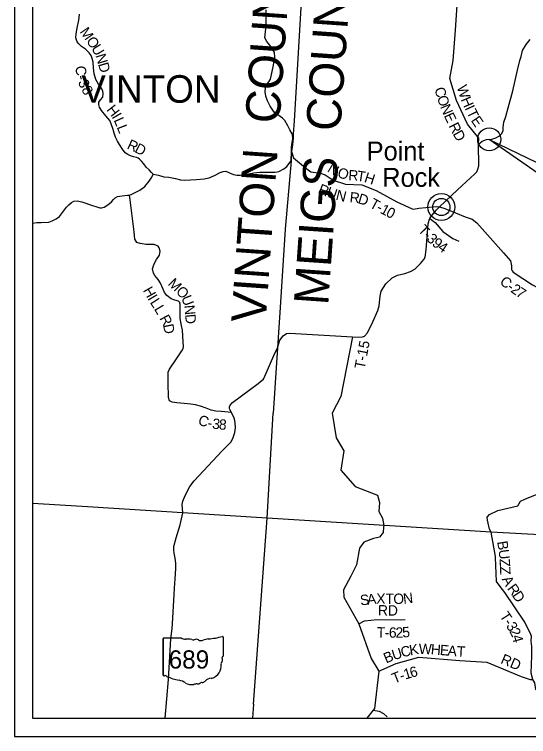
# Model space of a CAD drawing. Extents: x -84548 to 2262448, y -162180 to 525962.
# Drawn here: x -37475 to -22558, y 130056 to 150992 of the extents above; entities that cross this region are included whole.
import ezdxf

# ---------------------------------------------------------------- set-up
doc = ezdxf.new("R2010")
doc.units = 0
for name, color, linetype in [('GM_X_Adjacent_County_Text', 7, 'Continuous'), ('GM_X_City_Street', 7, 'Continuous'), ('GM_X_City_Street_Text', 7, 'Continuous'), ('GM_X_Corporation_Text', 7, 'Continuous'), ('GM_X_County', 7, 'Continuous'), ('GM_X_County_Road', 7, 'Continuous'), ('GM_X_Hydro', 7, 'Continuous'), ('GM_X_Major_Lake', 7, 'Continuous'), ('GM_X_Major_Lake_Text', 7, 'Continuous'), ('GM_X_Major_River', 7, 'Continuous'), ('GM_X_Minor_Lake', 7, 'Continuous'), ('GM_X_Minor_River_Text', 7, 'Continuous'), ('GM_X_Rail_Line', 7, 'Continuous'), ('GM_X_Section', 7, 'Continuous'), ('GM_X_Township_Road', 7, 'Continuous')]:
    doc.layers.add(name, color=color, linetype=linetype)

msp = doc.modelspace()

# ---------------------------------------------------------------- linework, layer by layer
at = {"layer": 'GM_X_Adjacent_County_Text'}
msp.add_circle((-23698, 147370), 334, dxfattribs=at)
at = {"layer": 'GM_X_City_Street'}
for p, q in [((-30138, 136391), (-29965, 139433)), ((-30539, 130996), (-30138, 136391))]:
    msp.add_line(p, q, dxfattribs=at)
at = {"layer": 'GM_X_County'}
for p, q in [((-37475, 167016), (-37475, 130056)), ((-36947, 166488), (-36947, 130584)), ((-36947, 166488), (-36947, 130584)), ((-36947, 130584), (-1043, 130584)), ((-36947, 130584), (-1043, 130584)), ((-37475, 130056), (-515, 130056))]:
    msp.add_line(p, q, dxfattribs=at)
at = {"layer": 'GM_X_Hydro'}
for p, q in [((-35513, 136724), (-36947, 136815)), ((-30138, 136391), (-35513, 136724)), ((-23639, 135977), (-30138, 136391)), ((-19190, 135747), (-23639, 135977)), ((-30539, 130996), (-30565, 130584))]:
    msp.add_line(p, q, dxfattribs=at)
at = {"layer": 'GM_X_Major_Lake'}
for p, q in [((-29155, 151361), (-29360, 147907)), ((-29360, 147907), (-29388, 147517)), ((-29390, 147404), (-29406, 147216)), ((-29388, 147517), (-29390, 147404)), ((-29406, 147216), (-29433, 147017)), ((-29433, 147017), (-29449, 146744)), ((-29449, 146744), (-29615, 144771)), ((-29615, 144771), (-29777, 142346)), ((-29777, 142346), (-29965, 139433))]:
    msp.add_line(p, q, dxfattribs=at)
at = {"layer": 'GM_X_Major_Lake_Text'}
for points in [[(-29843, 141330), (-29779, 141548), (-29675, 141670), (-29583, 141737), (-29482, 141751), (-27668, 141649), (-27506, 141639), (-27373, 141640), (-27315, 141664), (-27231, 141762), (-27076, 142081), (-26928, 142408), (-26892, 142539), (-26860, 142821), (-26834, 142972), (-26695, 143182), (-26515, 143353), (-26362, 143430), (-26152, 143482), (-25980, 143536), (-25856, 143605), (-25690, 143775), (-25594, 143884), (-25556, 143956), (-25532, 144165), (-25469, 144918), (-25441, 145031), (-25418, 145078), (-25397, 145119), (-25240, 145314), (-25139, 145410), (-24619, 145906), (-24113, 146368), (-24061, 146430), (-24029, 146508), (-24004, 146607), (-24006, 147234), (-23902, 147314), (-23774, 147362), (-23622, 147379), (-23506, 147415), (-23403, 147470), (-23339, 147529), (-23296, 147618), (-23293, 147718), (-23273, 147871), (-23219, 148036), (-23148, 148281), (-23019, 148778), (-22882, 149379), (-22811, 149652), (-22776, 149773), (-22732, 149942), (-22626, 150117), (-22507, 150261)], [(-33102, 130584), (-33004, 131710), (-32937, 132890), (-32902, 133187), (-32888, 133337), (-32836, 134164), (-32831, 134361), (-32811, 134631), (-32792, 134928), (-32788, 135084), (-32812, 135231), (-32842, 135376), (-32853, 135466), (-32847, 135570), (-32783, 135814), (-32667, 136192), (-32592, 136543), (-32605, 136788), (-32587, 136880), (-32523, 137040), (-32382, 137306), (-32256, 137471), (-31443, 138335), (-31190, 138600), (-31126, 138730), (-31078, 138871), (-31060, 139009), (-31066, 139152), (-31077, 139222), (-31098, 139291), (-31176, 139450), (-31222, 139541), (-31230, 139577), (-31232, 139611), (-31218, 139659), (-31148, 139737), (-30406, 140290), (-30284, 140384), (-30246, 140420), (-30170, 140591), (-29950, 141101), (-29843, 141330)]]:
    msp.add_lwpolyline(points, dxfattribs=at)
at = {"layer": 'GM_X_Major_River'}
for radius in [393, 249]:
    msp.add_circle((-25088, 145408), radius, dxfattribs=at)
at = {"layer": 'GM_X_Minor_Lake'}
for points in [[(-24006, 147234), (-24003, 147400), (-24326, 147809), (-24651, 148495), (-24842, 149138), (-24746, 149656), (-24677, 150538), (-24633, 151264)], [(-29433, 147017), (-29436, 147130), (-29431, 147221), (-29401, 147399), (-29404, 147494), (-29413, 147532), (-29485, 147642), (-29547, 147766), (-29634, 147916), (-29695, 147980), (-29938, 148161), (-30053, 148331), (-30133, 148485), (-30184, 148619), (-30198, 148751), (-30188, 148875), (-30161, 148953), (-30097, 149040), (-30043, 149118), (-29966, 149476), (-29921, 149751), (-29932, 149885), (-30040, 150061), (-30153, 150209), (-30205, 150315), (-30168, 150665), (-30174, 150977), (-30170, 151125)], [(-29433, 147017), (-29376, 146839), (-29261, 146738), (-29025, 146549), (-28879, 146426), (-28598, 146388), (-28462, 146340), (-28223, 146188), (-27874, 146074), (-27399, 146048), (-26982, 145890), (-26380, 145561), (-25933, 145359), (-25932, 145358)], [(-25932, 145358), (-25898, 145343), (-25742, 145377), (-25339, 145412), (-25215, 145420), (-25139, 145410)], [(-25418, 145078), (-25265, 144956), (-25048, 144702), (-24753, 144497), (-24584, 144417)], [(-27668, 141649), (-28005, 139915), (-28256, 139428), (-28138, 138720), (-27917, 138336), (-28005, 137775), (-27592, 137303), (-26943, 137052), (-26884, 136845), (-26898, 136580), (-26795, 136388), (-26757, 136176), (-26762, 136125)], [(-23687, 136067), (-23688, 136069), (-23747, 136328), (-23755, 136415), (-23692, 136491), (-23452, 136613), (-22869, 136745), (-22790, 136882), (-22666, 136939), (-22260, 137101), (-21781, 137046), (-21437, 137078), (-21126, 137044), (-20859, 137025), (-20194, 137164), (-19924, 137208)], [(-26762, 136125), (-26776, 135972), (-26886, 135833), (-27061, 135798), (-27341, 135694), (-27459, 135517), (-27548, 135030), (-27710, 134706), (-27931, 134307), (-27917, 134100), (-27480, 133323), (-27120, 132315), (-26901, 131953), (-27031, 130869), (-27071, 130817), (-27247, 130584)], [(-23516, 135249), (-23517, 135272), (-23639, 135977), (-23687, 136067)], [(-21591, 130584), (-21705, 130712), (-22344, 131416), (-22376, 131611), (-22433, 131714), (-22481, 131889), (-22467, 132399), (-22464, 132666), (-22479, 132817), (-22473, 132969), (-22495, 133014), (-22669, 133371), (-23242, 134235), (-23385, 134405), (-23487, 134553), (-23516, 135246), (-23516, 135249)], [(-27480, 133323), (-27319, 133406), (-26950, 133452), (-26271, 133436), (-26141, 133451)], [(-26901, 131953), (-26395, 132177), (-25743, 132354), (-24553, 132256), (-23768, 132217), (-22768, 131796), (-22510, 131713), (-22433, 131714)], [(-27071, 130817), (-26889, 130787), (-26763, 130721), (-26656, 130623)]]:
    msp.add_lwpolyline(points, dxfattribs=at)
at = {"layer": 'GM_X_Minor_River_Text'}
msp.add_line((-29449, 146744), (-29433, 147017), dxfattribs=at)
for points in [[(-33452, 146363), (-33500, 146405), (-33570, 146489), (-33651, 146566), (-33721, 146656), (-33789, 146738), (-33848, 146800), (-33882, 146828), (-33936, 146846), (-34024, 146868), (-34104, 146896), (-34184, 146927), (-34265, 146979), (-34343, 147089), (-34427, 147223), (-34486, 147317), (-34542, 147431), (-34581, 147553), (-34611, 147657), (-34668, 147817), (-34710, 147917), (-34824, 148049), (-34949, 148203), (-35011, 148307), (-35030, 148377), (-35028, 148453), (-34982, 148515), (-34914, 148597), (-34901, 148693), (-34911, 148777), (-34959, 148863), (-35034, 148973), (-35108, 149107), (-35161, 149269), (-35181, 149447), (-35192, 149608), (-35218, 149716), (-35247, 149798), (-35303, 149881), (-35415, 149983), (-35526, 150065), (-35606, 150135), (-35650, 150195), (-35691, 150309), (-35687, 150427), (-35656, 150589), (-35604, 150828), (-35583, 151002)], [(-36947, 144940), (-36827, 144955), (-36697, 144961), (-36477, 144972), (-36379, 145004), (-36263, 145066), (-36166, 145137), (-36048, 145285), (-35960, 145404), (-35900, 145476), (-35821, 145540), (-35753, 145580), (-35659, 145590), (-35523, 145563), (-35212, 145457), (-35088, 145412), (-35000, 145384), (-34944, 145380), (-34868, 145400), (-34760, 145469), (-34654, 145557), (-34598, 145625), (-34548, 145671), (-34480, 145716), (-34350, 145734), (-34194, 145750), (-34132, 145754), (-34068, 145777), (-33951, 145837), (-33835, 145901), (-33689, 146008), (-33563, 146158), (-33486, 146269), (-33452, 146363), (-33298, 146333), (-33142, 146287), (-32995, 146270), (-32797, 146232), (-32659, 146194), (-32539, 146187), (-32195, 146206), (-31971, 146228), (-31829, 146257), (-31671, 146323), (-31505, 146410), (-31419, 146440), (-31341, 146444), (-31237, 146402), (-31117, 146354), (-31020, 146327), (-30928, 146329), (-30734, 146361), (-30532, 146400), (-30352, 146418), (-30016, 146415), (-29906, 146420), (-29808, 146440), (-29656, 146516), (-29572, 146585), (-29449, 146744)], [(-31176, 139450), (-31373, 139469), (-31480, 139479), (-31630, 139494), (-31762, 139516), (-31914, 139572), (-32078, 139631), (-32219, 139677), (-32355, 139693), (-32551, 139710), (-32759, 139730), (-32901, 139748), (-32941, 139765), (-32978, 139793), (-33008, 139883), (-33011, 140310), (-33016, 140502), (-33012, 140618), (-32973, 140712), (-32774, 141009), (-32614, 141236), (-32576, 141304), (-32567, 141354), (-32577, 141498), (-32602, 141836), (-32631, 141972), (-32663, 142173), (-32666, 142335), (-32667, 142535), (-32669, 142595), (-32671, 142621), (-32677, 142643), (-32711, 142681), (-32823, 142711), (-32925, 142746), (-33056, 142840), (-33120, 142926), (-33169, 143050), (-33235, 143196), (-33308, 143308), (-33402, 143420), (-33442, 143486), (-33473, 143620), (-33421, 143760), (-33348, 143889), (-33270, 144017), (-33250, 144127), (-33271, 144221), (-33309, 144273), (-33419, 144317), (-33655, 144326), (-33823, 144348), (-33920, 144380), (-33978, 144474), (-33999, 144686), (-34114, 145620), (-34132, 145754)], [(-25139, 145410), (-24987, 145364), (-24674, 145235), (-24402, 145124), (-24195, 145054), (-24059, 144947), (-23288, 144083), (-23078, 143852), (-23056, 143706), (-23053, 143601), (-23035, 143557), (-23002, 143523), (-22447, 143149), (-22209, 143029), (-21871, 142513), (-21621, 141908), (-21398, 141679), (-21156, 141593), (-21000, 141614)]]:
    msp.add_lwpolyline(points, dxfattribs=at)
at = {"layer": 'GM_X_Rail_Line'}
for p, q in [((-33160, 132895), (-33160, 131838)), ((-33160, 131838), (-33160, 132895)), ((-33160, 131838), (-33160, 132895)), ((-33143, 132913), (-32633, 132913)), ((-31420, 132939), (-31420, 132387)), ((-31420, 132387), (-31420, 132387))]:
    msp.add_line(p, q, dxfattribs=at)
for centre, major_axis, start_param, end_param in [((-32040, 134354), (1845, 0), 4.814394, 5.042369), ((-31439, 132942), (19.4, 0), 6.141152, 7.989035), ((-33140, 132897), (20.2, 0), 1.712693, 3.28349), ((-32512, 133036), (196, 0), 4.042523, 4.731795), ((-32447, 132320), (702, 0), 1.404758, 1.657858), ((-32288, 132903), (56.4, 0), 3.836095, 5.185415), ((-32205, 132781), (117, 0), 0.950623, 2.079405), ((-32054, 132948), (141, 0), 4.081561, 5.145723), ((-31805, 132591), (371, 0), 1.699011, 2.107814), ((-31424, 132346), (30, 0), 1.883978, 3.671073), ((-31615, 132276), (180, 0), 5.934695, 6.695948), ((-31441, 132385), (20.7, 0), 5.05454, 6.418171), ((-31937, 132085), (462, 0), 5.101752, 6.440018), ((-31351, 132155), (131, 0), 2.387724, 3.262537), ((-33140, 131836), (20.3, 0), 3.00124, 4.508301), ((-33137, 131944), (155, 0), 4.665946, 4.897461), ((-33105, 131777), (56, 0), 0.519207, 1.627899), ((-32399, 132727), (1333, 0), 4.195997, 4.488961), ((-31742, 131542), (253, 0), 1.647645, 2.488434), ((-32796, 131364), (417, 0), 0.823519, 1.323587), ((-32345, 131772), (265, 0), 4.026481, 4.996735), ((-32192, 131407), (217, 0), 1.495662, 1.94098), ((-32173, 131693), (141, 0), 4.691044, 5.507374), ((-32045, 131591), (39.7, 0), 1.147584, 2.315152), ((-32062, 131736), (149, 0), 4.937069, 5.64225)]:
    msp.add_ellipse(centre, major_axis=major_axis, ratio=0.8, start_param=start_param, end_param=end_param, dxfattribs=at)
at = {"layer": 'GM_X_Section'}
msp.add_lwpolyline([(-20640, 145240), (-23698, 147370), (-19294, 145240)], close=True, dxfattribs=at)

# ---------------------------------------------------------------- texts
at = {"layer": 'GM_X_Adjacent_County_Text'}
for s, p in [('Point', (-27254, 146757)), ('Rock', (-26803, 145994))]:
    msp.add_text(s, height=550, rotation=0, dxfattribs=at).set_placement(p)
at = {"layer": 'GM_X_City_Street_Text'}
for s, p in [('VINTON  COUNTY', (-30187, 142028)), ('MEIGS  COUNTY', (-28372, 142544))]:
    msp.add_text(s, height=1000, rotation=86.0177, dxfattribs=at).set_placement(p)
at = {"layer": 'GM_X_Corporation_Text'}
msp.add_text('VINTON', height=800, rotation=0, dxfattribs=at).set_placement((-35536, 148431))
at = {"layer": 'GM_X_County_Road'}
for s, rotation, p in [('M', 305.1287, (-35592, 150488)), ('O', 305.0905, (-35405, 150222)), ('U', 301.3374, (-35256, 150010)), ('N', 286.739, (-35127, 149803)), ('C', 274.8453, (-35704, 149491)), ('D', 286.3057, (-35051, 149551)), ('3', 290.86, (-35635, 149037)), ('-', 283.1188, (-35676, 149199)), ('8', 301.5722, (-35542, 148809)), ('H', 307.8986, (-34816, 148226)), ('I', 300.289, (-34660, 148027)), ('L', 294.0574, (-34601, 147928)), ('L', 291.343, (-34511, 147726)), ('R', 335.4914, (-34230, 147111)), ('D', 332.7768, (-34009, 147011)), ('M', 315.3133, (-33040, 143168)), ('C', 320.021, (-23418, 143206)), ('H', 299.3861, (-33755, 142995)), ('O', 315, (-32809, 142939)), ('-', 326.1692, (-23201, 143026)), ('2', 325.9982, (-23099, 142958)), ('7', 326.3742, (-22944, 142853)), ('I', 300.2356, (-33623, 142760)), ('U', 291.1777, (-32640, 142780)), ('L', 302.9032, (-33553, 142641)), ('L', 300.4221, (-33433, 142455)), ('N', 275.5091, (-32549, 142555)), ('R', 298.1345, (-33274, 142185)), ('D', 275.326, (-32524, 142292)), ('D', 281.3221, (-33165, 141989)), ('C', 340.2023, (-32172, 139113)), ('3', 352.5968, (-31750, 138988)), ('8', 355.0635, (-31553, 138963)), ('-', 348.6688, (-31893, 139016))]:
    msp.add_text(s, height=300, rotation=rotation, dxfattribs=at).set_placement(p)
at = {"layer": 'GM_X_Rail_Line'}
msp.add_text('689', height=528, dxfattribs=at).set_placement((-33001, 132027))
at = {"layer": 'GM_X_Township_Road'}
for s, rotation, p in [('C', 286.663, (-25294, 148834)), ('W', 287.4611, (-24644, 148890)), ('O', 288.5918, (-25220, 148588)), ('H', 293.1972, (-24529, 148528)), ('N', 292.5151, (-25128, 148316)), ('I', 295.1151, (-24420, 148275)), ('T', 296.0744, (-24366, 148159)), ('E', 295.0778, (-25021, 148059)), ('E', 304.4273, (-24243, 147917)), ('R', 296.5174, (-24883, 147765)), ('D', 299.1537, (-24766, 147531)), ('N', 329.3261, (-28419, 146447)), ('O', 342.0592, (-28126, 146283)), ('R', 356.3874, (-27794, 146186)), ('T', 351.1711, (-27556, 146171)), ('H', 341.921, (-27346, 146140)), ('R', 339.346, (-28684, 145808)), ('U', 341.0357, (-28444, 145718)), ('N', 345.9273, (-28168, 145624)), ('R', 354.1156, (-27759, 145547)), ('D', 342.9988, (-27529, 145524)), ('T', 331.5113, (-27194, 145414)), ('-', 331.5767, (-26997, 145307)), ('1', 331.7793, (-26887, 145248)), ('0', 332.8943, (-26719, 145158)), ('T', 313.6968, (-25787, 144721)), ('-', 314.2524, (-25630, 144556)), ('3', 316.2178, (-25536, 144460)), ('9', 321.6631, (-25379, 144312)), ('4', 326.0153, (-25214, 144182)), ('T-15', 78.9675, (-27319, 140695)), ('B', 279.0119, (-23471, 135704)), ('U', 276.9362, (-23433, 135464)), ('Z', 273.1644, (-23402, 135207)), ('Z', 272.3578, (-23389, 134984)), ('A', 298.0937, (-23342, 134619)), ('R', 306.4686, (-23192, 134345)), ('X', 359.4827, (-26977, 133906)), ('T', 358.9114, (-26713, 133903)), ('O', 0.582, (-26480, 133899)), ('N', 6.2776, (-26183, 133904)), ('D', 303.8522, (-23048, 134150)), ('S', 6.4517, (-27431, 133856)), ('A', 6.0656, (-27230, 133878)), ('RD', 359.0128, (-26930, 133569)), ('T', 303.0357, (-23409, 133554)), ('-', 302.7699, (-23287, 133366)), ('3', 301.7715, (-23221, 133264)), ('T', 359.5586, (-26959, 132928)), ('6', 359.0041, (-26612, 132923)), ('2', 1.0757, (-26415, 132920)), ('5', 4.7587, (-26210, 132925)), ('2', 297.7451, (-23126, 133111)), ('-', 358.8993, (-26736, 132926)), ('4', 285.4601, (-23047, 132964)), ('K', 9.951, (-25991, 132407)), ('W', 358.3923, (-25747, 132452)), ('H', 355.3613, (-25403, 132442)), ('B', 22.8683, (-26690, 132173)), ('U', 17.4897, (-26470, 132266)), ('C', 15.1149, (-26222, 132345)), ('E', 355.364, (-25140, 132421)), ('A', 355.4759, (-24916, 132403)), ('T', 356.5429, (-24647, 132381)), ('RD', 337.1891, (-23390, 132188)), ('T', 22.0823, (-26454, 131586)), ('1', 16.3643, (-26137, 131707)), ('6', 15.4121, (-25961, 131758)), ('-', 18.2362, (-26251, 131669))]:
    msp.add_text(s, height=300, rotation=rotation, dxfattribs=at).set_placement(p)

doc.saveas('drawing.dxf')
